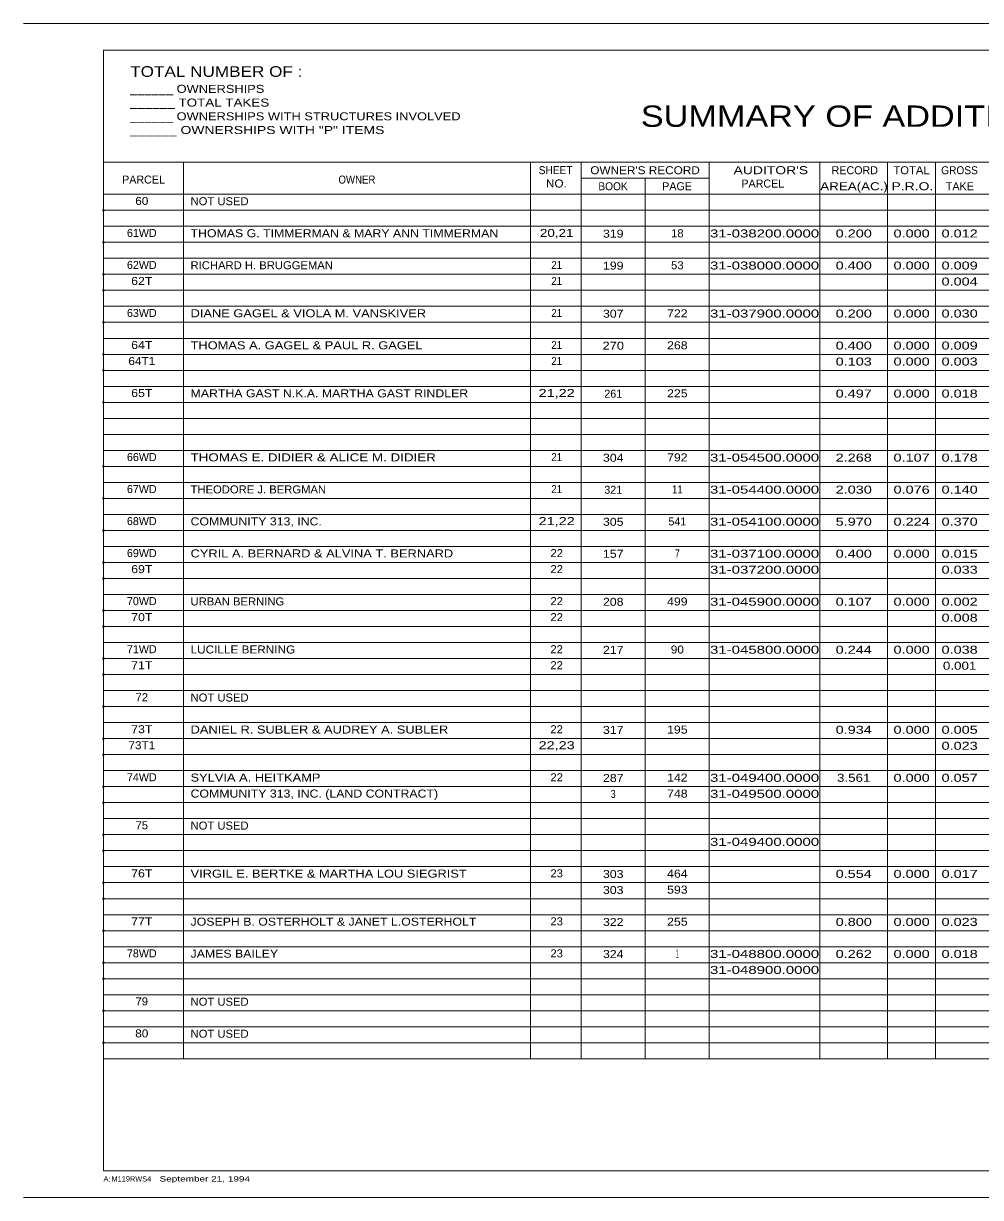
# Model space of a CAD drawing. Extents: x -1 to 34.5, y 0 to 22.
# Drawn here: x -1 to 16.94, y 0 to 22 of the extents above; entities that cross this region are included whole.
import ezdxf
from ezdxf.enums import TextEntityAlignment as Align

# ---------------------------------------------------------------- set-up
doc = ezdxf.new("R2010")
doc.units = 0
doc.header["$LTSCALE"] = 0.06
doc.header["$PDMODE"] = 32
doc.header["$PDSIZE"] = 0.03
doc.layers.add('1', color=7, linetype='Continuous', lineweight=13)
doc.layers.add('60', color=7, linetype='Continuous', lineweight=13)

msp = doc.modelspace()

# ---------------------------------------------------------------- linework, layer by layer
at = {"layer": '1'}
for p in [(0.5, 18.5), (0.5, 17.9), (0.5, 17.3), (0.5, 17), (0.5, 16.4), (0.5, 15.8), (0.5, 15.5), (0.5, 14.9), (0.5, 13.7), (0.5, 13.1), (0.5, 12.5), (0.5, 11.9), (0.5, 11.6), (0.5, 11), (0.5, 10.7), (0.5, 10.1), (0.5, 9.8), (0.5, 9.2), (0.5, 8.6), (0.5, 8.3), (0.5, 7.7), (0.5, 7.4), (0.5, 6.8), (0.5, 6.5), (0.5, 5.9), (0.5, 5.6), (0.5, 5), (0.5, 4.4), (0.5, 4.1), (0.5, 3.5), (0.5, 2.9)]:
    msp.add_point(p, dxfattribs=at)
at = {"layer": '60'}
for p, q in [((-1, 22), (34.5, 22)), ((0.5, 21.5), (34, 21.5)), ((0.5, 0.5), (0.5, 21.5)), ((0.5, 19.4), (34, 19.4)), ((2, 2.6), (2, 19.4)), ((8.5, 2.6), (8.5, 19.4)), ((9.45025, 2.6), (9.45025, 19.4)), ((11.85025, 2.6), (11.85025, 19.4)), ((13.92625, 2.6), (13.92625, 19.4)), ((15.19617, 2.6), (15.19617, 19.4)), ((16.09617, 2.6), (16.09617, 19.4)), ((9.45025, 19.1), (11.85025, 19.1)), ((10.65025, 2.6), (10.65025, 19.1)), ((0.5, 18.8), (34, 18.8)), ((0.5, 18.5), (34, 18.5)), ((0.5, 18.2), (34, 18.2)), ((0.5, 17.9), (34, 17.9)), ((0.5, 17.6), (34, 17.6)), ((0.5, 17.3), (34, 17.3)), ((0.5, 17), (34, 17)), ((0.5, 16.7), (34, 16.7)), ((0.5, 16.4), (34, 16.4)), ((0.5, 16.1), (34, 16.1)), ((0.5, 15.8), (34, 15.8)), ((0.5, 15.5), (34, 15.5)), ((0.5, 15.2), (34, 15.2)), ((0.5, 14.9), (34, 14.9)), ((0.5, 14.6), (34, 14.6)), ((0.5, 14.3), (34, 14.3)), ((0.5, 14), (34, 14)), ((0.5, 13.7), (34, 13.7)), ((0.5, 13.4), (34, 13.4)), ((0.5, 13.1), (34, 13.1)), ((0.5, 12.8), (34, 12.8)), ((0.5, 12.5), (34, 12.5)), ((0.5, 12.2), (34, 12.2)), ((0.5, 11.9), (34, 11.9)), ((0.5, 11.6), (34, 11.6)), ((0.5, 11.3), (34, 11.3)), ((0.5, 11), (34, 11)), ((0.5, 10.7), (34, 10.7)), ((0.5, 10.4), (34, 10.4)), ((0.5, 10.1), (34, 10.1)), ((0.5, 9.8), (34, 9.8)), ((0.5, 9.5), (34, 9.5)), ((0.5, 9.2), (34, 9.2)), ((0.5, 8.9), (34, 8.9)), ((0.5, 8.6), (34, 8.6)), ((0.5, 8.3), (34, 8.3)), ((0.5, 8), (34, 8)), ((0.5, 7.7), (34, 7.7)), ((0.5, 7.4), (34, 7.4)), ((0.5, 7.1), (34, 7.1)), ((0.5, 6.8), (34, 6.8)), ((0.5, 6.5), (34, 6.5)), ((0.5, 6.2), (34, 6.2)), ((0.5, 5.9), (34, 5.9)), ((0.5, 5.6), (34, 5.6)), ((0.5, 5.3), (34, 5.3)), ((0.5, 5), (34, 5)), ((0.5, 4.7), (34, 4.7)), ((0.5, 4.4), (34, 4.4)), ((0.5, 4.1), (34, 4.1)), ((0.5, 3.8), (34, 3.8)), ((0.5, 3.5), (34, 3.5)), ((0.5, 3.2), (34, 3.2)), ((0.5, 2.9), (34, 2.9)), ((0.5, 2.6), (34, 2.6)), ((-1, 0), (34.5, 0))]:
    msp.add_line(p, q, dxfattribs=at)
msp.add_lwpolyline([(34, 21.5), (34, 0.5), (0.5, 0.5)], dxfattribs=at)

# ---------------------------------------------------------------- texts
at = {"layer": '1'}
for s, width, p in [('60', 1.1, (1.21767, 18.60025)), ('20,21', 1.25, (8.9935, 18.00025)), ('319', 1.15, (10.05379, 17.9875)), ('18', 1.05, (11.25517, 17.99383)), ('31-038200.0000', 1.4, (12.89025, 17.99)), ('0.200', 1.35, (14.56129, 17.99)), ('0.000', 1.35, (15.64621, 17.99)), ('0.012', 1.35, (16.54612, 17.99)), ('21', 0.9, (8.99354, 17.40025)), ('199', 1.15, (10.05379, 17.3875)), ('53', 1.05, (11.25517, 17.39383)), ('31-038000.0000', 1.4, (12.89025, 17.39)), ('0.400', 1.35, (14.56129, 17.39)), ('0.000', 1.35, (15.64621, 17.39)), ('0.009', 1.35, (16.54612, 17.39)), ('62T', 1.15, (1.21771, 17.10025)), ('21', 0.9, (8.99354, 17.10025)), ('0.004', 1.35, (16.54612, 17.09)), ('21', 0.9, (8.99354, 16.50025)), ('307', 1.15, (10.05379, 16.4875)), ('722', 1.15, (11.25512, 16.49383)), ('31-037900.0000', 1.4, (12.89025, 16.49)), ('0.200', 1.35, (14.56129, 16.49)), ('0.000', 1.35, (15.64621, 16.49)), ('0.030', 1.35, (16.54621, 16.49)), ('64T', 1.15, (1.21771, 15.90025)), ('21', 0.9, (8.99354, 15.90025)), ('270', 1.2, (10.05387, 15.8875)), ('268', 1.15, (11.25512, 15.89383)), ('0.400', 1.35, (14.56129, 15.89)), ('0.000', 1.35, (15.64621, 15.89)), ('0.009', 1.35, (16.54612, 15.89)), ('64T1', 1.1, (1.21767, 15.60025)), ('21', 0.9, (8.99354, 15.60025)), ('0.103', 1.35, (14.56121, 15.59)), ('0.000', 1.35, (15.64621, 15.59)), ('0.003', 1.35, (16.54612, 15.59)), ('65T', 1.15, (1.21771, 15.00025)), ('21,22', 1.35, (8.99346, 15.00025)), ('225', 1.15, (11.25512, 14.99383)), ('0.497', 1.35, (14.56121, 14.99)), ('0.000', 1.35, (15.64621, 14.99)), ('0.018', 1.35, (16.54612, 14.99)), ('21', 0.9, (8.99354, 13.80025)), ('304', 1.15, (10.05379, 13.7875)), ('792', 1.15, (11.25512, 13.79383)), ('31-054500.0000', 1.4, (12.89025, 13.79)), ('2.268', 1.35, (14.56121, 13.79)), ('0.107', 1.35, (15.64612, 13.79)), ('0.178', 1.35, (16.54612, 13.79)), ('21', 0.9, (8.99354, 13.20025)), ('11', 0.9, (11.25521, 13.19383)), ('31-054400.0000', 1.4, (12.89025, 13.19)), ('2.030', 1.35, (14.56129, 13.19)), ('0.076', 1.35, (15.64621, 13.19)), ('0.140', 1.35, (16.54621, 13.19)), ('21,22', 1.35, (8.99346, 12.60025)), ('305', 1.15, (10.05379, 12.5875)), ('31-054100.0000', 1.4, (12.89025, 12.59)), ('5.970', 1.35, (14.56129, 12.59)), ('0.224', 1.35, (15.64612, 12.59)), ('0.370', 1.35, (16.54621, 12.59)), ('22', 1.05, (8.9935, 12.00025)), ('157', 1.15, (10.05379, 11.9875)), ('7', 0.8, (11.25517, 11.99383)), ('31-037100.0000', 1.4, (12.89025, 11.99)), ('0.400', 1.35, (14.56129, 11.99)), ('0.000', 1.35, (15.64621, 11.99)), ('0.015', 1.35, (16.54612, 11.99)), ('69T', 1.15, (1.21771, 11.70025)), ('22', 1.05, (8.9935, 11.70025)), ('31-037200.0000', 1.4, (12.89025, 11.69)), ('0.033', 1.35, (16.54612, 11.69)), ('22', 1.05, (8.9935, 11.10025)), ('208', 1.15, (10.05379, 11.0875)), ('499', 1.15, (11.25512, 11.09383)), ('31-045900.0000', 1.4, (12.89025, 11.09)), ('0.107', 1.35, (14.56121, 11.09)), ('0.000', 1.35, (15.64621, 11.09)), ('0.002', 1.35, (16.54612, 11.09)), ('70T', 1.15, (1.21771, 10.80025)), ('22', 1.05, (8.9935, 10.80025)), ('0.008', 1.35, (16.54612, 10.79)), ('22', 1.05, (8.9935, 10.20025)), ('90', 1.1, (11.25517, 10.19383)), ('31-045800.0000', 1.4, (12.89025, 10.19)), ('0.244', 1.35, (14.56121, 10.19)), ('0.000', 1.35, (15.64621, 10.19)), ('0.038', 1.35, (16.54612, 10.19)), ('217', 1.15, (10.05379, 10.1875)), ('71T', 1.15, (1.21771, 9.90025)), ('22', 1.05, (8.9935, 9.90025)), ('0.001', 1.25, (16.54617, 9.89)), ('72', 1.05, (1.21767, 9.30025)), ('73T', 1.15, (1.21771, 8.70025)), ('22', 1.05, (8.9935, 8.70025)), ('317', 1.15, (10.05379, 8.6875)), ('195', 1.15, (11.25512, 8.69383)), ('0.934', 1.35, (14.56121, 8.69)), ('0.000', 1.35, (15.64621, 8.69)), ('0.005', 1.35, (16.54612, 8.69)), ('73T1', 1.1, (1.21767, 8.40025)), ('22,23', 1.35, (8.99346, 8.40025)), ('0.023', 1.35, (16.54612, 8.39)), ('22', 1.05, (8.9935, 7.80025)), ('287', 1.15, (10.05379, 7.7875)), ('142', 1.15, (11.25512, 7.79383)), ('31-049400.0000', 1.4, (12.89025, 7.79)), ('3.561', 1.25, (14.56125, 7.79)), ('0.000', 1.35, (15.64621, 7.79)), ('0.057', 1.35, (16.54612, 7.79)), ('3', 0.8, (10.05383, 7.4875)), ('748', 1.15, (11.25512, 7.49383)), ('31-049500.0000', 1.4, (12.89025, 7.49)), ('75', 1.05, (1.21767, 6.90025)), ('31-049400.0000', 1.4, (12.89025, 6.59)), ('76T', 1.15, (1.21771, 6.00025)), ('23', 1.05, (8.9935, 6.00025)), ('303', 1.15, (10.05379, 5.9875)), ('464', 1.15, (11.25512, 5.99383)), ('0.554', 1.35, (14.56121, 5.99)), ('0.000', 1.35, (15.64621, 5.99)), ('0.017', 1.35, (16.54612, 5.99)), ('303', 1.15, (10.05379, 5.6875)), ('593', 1.15, (11.25512, 5.69383)), ('77T', 1.15, (1.21771, 5.10025)), ('23', 1.05, (8.9935, 5.10025)), ('322', 1.15, (10.05379, 5.0875)), ('255', 1.15, (11.25512, 5.09383)), ('0.800', 1.35, (14.56129, 5.09)), ('0.000', 1.35, (15.64621, 5.09)), ('0.023', 1.35, (16.54612, 5.09)), ('23', 1.05, (8.9935, 4.50025)), ('324', 1.15, (10.05379, 4.4875)), ('1', 0.45, (11.25512, 4.49383)), ('31-048800.0000', 1.4, (12.89025, 4.49)), ('0.262', 1.35, (14.56121, 4.49)), ('0.000', 1.35, (15.64621, 4.49)), ('0.018', 1.35, (16.54612, 4.49)), ('31-048900.0000', 1.4, (12.89025, 4.19)), ('79', 1.05, (1.21767, 3.60025)), ('80', 1.1, (1.21767, 3.00025))]:
    msp.add_text(s, height=0.15, dxfattribs=dict(at, width=width)).set_placement(p, align=Align.CENTER)
for s, height, width, p in [('NOT USED', 0.15, 1.05, (2.13167, 18.59433)), ('THOMAS G. TIMMERMAN & MARY ANN TIMMERMAN', 0.15, 1.15, (2.13167, 17.99433)), ('RICHARD H. BRUGGEMAN', 0.15, 1.05, (2.13167, 17.39433)), ('DIANE GAGEL & VIOLA M. VANSKIVER', 0.15, 1.2, (2.13167, 16.49433)), ('THOMAS A. GAGEL & PAUL R. GAGEL', 0.15, 1.2, (2.13167, 15.89433)), ('MARTHA GAST N.K.A. MARTHA GAST RINDLER', 0.15, 1.15, (2.13167, 14.99433)), ('THOMAS E. DIDIER & ALICE M. DIDIER', 0.15, 1.25, (2.13167, 13.79433)), ('THEODORE J. BERGMAN', 0.15, 1.05, (2.13167, 13.19433)), ('COMMUNITY 313, INC.', 0.15, 1.15, (2.13167, 12.59433)), ('CYRIL A. BERNARD & ALVINA T. BERNARD', 0.15, 1.2, (2.13167, 11.99433)), ('URBAN BERNING', 0.15, 1.05, (2.13167, 11.09433)), ('LUCILLE BERNING', 0.15, 1.1, (2.13167, 10.19433)), ('NOT USED', 0.15, 1.05, (2.13167, 9.29433)), ('DANIEL R. SUBLER & AUDREY A. SUBLER', 0.15, 1.2, (2.13167, 8.69433)), ('SYLVIA A. HEITKAMP', 0.15, 1.2, (2.13167, 7.79433)), ('COMMUNITY 313, INC. (LAND CONTRACT)', 0.15, 1.15, (2.13167, 7.49433)), ('NOT USED', 0.15, 1.05, (2.13167, 6.89433)), ('VIRGIL E. BERTKE & MARTHA LOU SIEGRIST', 0.15, 1.2, (2.13167, 5.99433)), ('JOSEPH B. OSTERHOLT & JANET L.OSTERHOLT', 0.15, 1.15, (2.13167, 5.09433)), ('JAMES BAILEY', 0.15, 1.15, (2.13167, 4.49433)), ('NOT USED', 0.15, 1.05, (2.13167, 3.59433)), ('NOT USED', 0.15, 1.05, (2.13167, 2.99433)), ('September 21, 1994', 0.1, 1.4, (1.55, 0.3))]:
    msp.add_text(s, height=height, dxfattribs=dict(at, width=width)).set_placement(p)
for s, p in [('61WD', (1.21762, 18.00025)), ('62WD', (1.21762, 17.40025)), ('63WD', (1.21762, 16.50025)), ('261', (10.05383, 14.9875)), ('66WD', (1.21762, 13.80025)), ('67WD', (1.21762, 13.20025)), ('321', (10.05383, 13.1875)), ('68WD', (1.21762, 12.60025)), ('541', (11.25517, 12.59383)), ('69WD', (1.21762, 12.00025)), ('70WD', (1.21762, 11.10025)), ('71WD', (1.21762, 10.20025)), ('74WD', (1.21762, 7.80025)), ('78WD', (1.21762, 4.50025))]:
    msp.add_text(s, height=0.15, dxfattribs=at).set_placement(p, align=Align.CENTER)
for s, p in [('A:', (0.5, 0.3)), ('M119RWS4', (0.65, 0.3))]:
    msp.add_text(s, height=0.1, dxfattribs=at).set_placement(p)
at = {"layer": '60'}
for s, height, width, p in [('TOTAL NUMBER OF :', 0.2, 1.2, (1, 21)), ('______ OWNERSHIPS', 0.15, 1.2, (1, 20.7)), ('______ TOTAL TAKES', 0.15, 1.25, (1, 20.44283)), ('______ OWNERSHIPS WITH STRUCTURES INVOLVED', 0.15, 1.2, (1, 20.18575)), ('______ OWNERSHIPS WITH "P" ITEMS', 0.15, 1.3, (1, 19.92858)), ("AUDITOR'S ", 0.15, 1.3, (12.30883, 19.176)), (' NO.', 0.15, 1.1, (8.73083, 18.92683))]:
    msp.add_text(s, height=height, dxfattribs=dict(at, width=width)).set_placement(p)
for s, height, width, p in [('SUMMARY OF ADDITIONAL RIGHT-OF-WAY', 0.4, 1.2, (17.2385, 20.06342)), ('OWNER', 0.15, 0.9, (5.25004, 19)), ('SHEET', 0.15, 0.95, (8.97467, 19.17683)), ("OWNER'S RECORD", 0.15, 1.1, (10.65025, 19.175)), ('TOTAL', 0.15, 1.05, (15.64387, 19.175)), ('GROSS', 0.15, 0.95, (16.54367, 19.175)), ('BOOK', 0.15, 0.95, (10.05029, 18.875)), ('AREA(AC.)', 0.15, 1.25, (14.56738, 18.875)), ('P.R.O.', 0.15, 1.3, (15.66092, 18.875))]:
    msp.add_text(s, height=height, dxfattribs=dict(at, width=width)).set_placement(p, align=Align.CENTER)
for s, p in [('PARCEL', (1.25004, 19)), ('RECORD', (14.58121, 19.175)), ('PAGE', (11.25025, 18.875)), ('TAKE', (16.55008, 18.875))]:
    msp.add_text(s, height=0.15, dxfattribs=at).set_placement(p, align=Align.CENTER)
msp.add_text('PARCEL', height=0.15, dxfattribs=at).set_placement((12.45575, 18.926))

doc.saveas('drawing.dxf')
